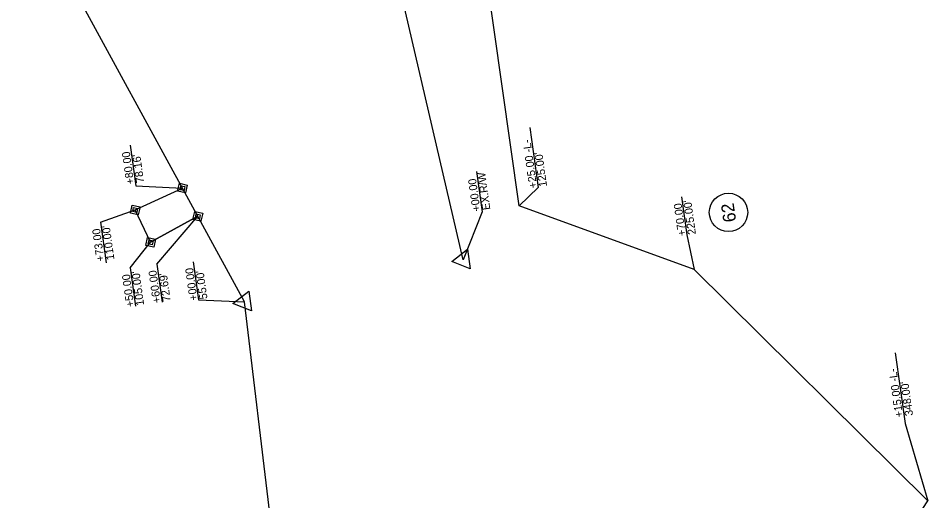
# Model space of a CAD drawing. Extents: x 474184 to 481900, y 489262 to 505659.
# Drawn here: x 477684 to 478252, y 498861 to 499163 of the extents above; entities that cross this region are included whole.
import ezdxf

# ---------------------------------------------------------------- set-up
doc = ezdxf.new("R2010")
doc.units = 0
for name, color, linetype in [('Prop Drainage Structure Outlet Berm Ditch 850 10 Label', 7, 'Continuous'), ('Prop Drainage Structure Pipe CSP 15in', 7, 'Continuous'), ('Prop Drainage Structure Pipe RCP 18in Class IV', 7, 'Continuous'), ('Prop Drainage Structure Pipe RCP 18in Class IV Label', 7, 'Continuous'), ('Prop Drainage Structure Pipe Side Drain 15in Label', 7, 'Continuous'), ('Prop Drainage Structure Pipe Stub Out CELL', 7, 'Continuous'), ('Prop Drainage Structure Plot Symbol 50 Scale', 7, 'Continuous'), ('Prop Earthen Structure Base Ditch Lateral Detail Label', 7, 'Continuous'), ('Prop Earthen Structure False Sump Label', 7, 'Continuous')]:
    doc.layers.add(name, color=color, linetype=linetype)

msp = doc.modelspace()

# ---------------------------------------------------------------- linework, layer by layer
at = {"layer": 'Prop Drainage Structure Outlet Berm Ditch 850 10 Label'}
msp.add_line((477796.28, 499038.73), (477766.76, 499022.46), dxfattribs=at)
msp.add_lwpolyline([(477766.76, 499022.46), (477757.15, 499042.69), (477786.68, 499056.34)], dxfattribs=at)
at = {"layer": 'Prop Drainage Structure Pipe CSP 15in'}
msp.add_line((478127.82, 499041.16), (478127.82, 499041.16), dxfattribs=at)
msp.add_circle((478127.82, 499041.16), 12, dxfattribs=at)
at = {"layer": 'Prop Drainage Structure Pipe RCP 18in Class IV'}
for p, q in [((477786.68, 499056.34), (477786.68, 499056.34)), ((477757.15, 499042.69), (477757.15, 499042.69)), ((477796.28, 499038.73), (477796.28, 499038.73)), ((477766.76, 499022.46), (477766.76, 499022.46)), ((477962.07, 499011.55), (477962.07, 499011.55)), ((477825.37, 498985.31), (477825.37, 498985.31))]:
    msp.add_line(p, q, dxfattribs=at)
for points in [[(477964.78, 499018.23), (477966.49, 499005.87), (477954.92, 499010.54)], [(477828.09, 498992), (477829.8, 498979.64), (477818.23, 498984.31)]]:
    msp.add_lwpolyline(points, close=True, dxfattribs=at)
at = {"layer": 'Prop Drainage Structure Pipe RCP 18in Class IV Label'}
for points in [[(477783.65, 499054.39), (477784.74, 499059.37), (477789.71, 499058.28), (477788.63, 499053.31)], [(477785.17, 499055.36), (477785.71, 499057.85), (477788.2, 499057.31), (477787.66, 499054.82)], [(477754.12, 499040.75), (477755.2, 499045.72), (477760.18, 499044.64), (477759.09, 499039.66)], [(477755.63, 499041.72), (477756.18, 499044.21), (477758.66, 499043.66), (477758.12, 499041.18)], [(477793.25, 499036.78), (477794.33, 499041.76), (477799.31, 499040.67), (477798.22, 499035.7)], [(477794.76, 499037.76), (477795.3, 499040.24), (477797.79, 499039.7), (477797.25, 499037.21)], [(477763.73, 499020.52), (477764.82, 499025.49), (477769.79, 499024.4), (477768.71, 499019.43)], [(477765.25, 499021.49), (477765.79, 499023.97), (477768.28, 499023.43), (477767.74, 499020.94)]]:
    msp.add_lwpolyline(points, close=True, dxfattribs=at)
at = {"layer": 'Prop Drainage Structure Pipe Side Drain 15in Label'}
for p, q in [((477962.07, 499011.55), (477915.07, 499214.11)), ((477935.51, 498068.61), (477825.37, 498985.31))]:
    msp.add_line(p, q, dxfattribs=at)
msp.add_lwpolyline([(477825.37, 498985.31), (477684.05, 499244.74)], dxfattribs=at)
at = {"layer": 'Prop Drainage Structure Pipe Stub Out CELL'}
msp.add_line((478230.71, 498827.55), (478252.33, 498860.85), dxfattribs=at)
for points in [[(477997.01, 499045.21), (477970.76, 499230.34)], [(478252.33, 498860.85), (478106.38, 499005.46), (477997.01, 499045.21)]]:
    msp.add_lwpolyline(points, dxfattribs=at)
at = {"layer": 'Prop Drainage Structure Plot Symbol 50 Scale'}
for p, q in [((477970.34, 499066.72), (477973.86, 499041.45)), ((477973.86, 499041.45), (477962.07, 499011.55)), ((477793.42, 499010.26), (477796.73, 498986.44))]:
    msp.add_line(p, q, dxfattribs=at)
msp.add_lwpolyline([(477796.73, 498986.44), (477825.37, 498985.31)], dxfattribs=at)
at = {"layer": 'Prop Earthen Structure Base Ditch Lateral Detail Label'}
for p, q in [((477753.99, 499083.13), (477757.51, 499057.83)), ((477796.28, 499038.73), (477766.76, 499022.46)), ((477766.76, 499022.46), (477796.28, 499038.73)), ((477735.41, 499034.99), (477738.93, 499009.69)), ((477764.51, 499034.18), (477764.51, 499034.18)), ((477754.02, 499006.45), (477757.33, 498982.63)), ((477770.58, 499008.9), (477773.9, 498985.08))]:
    msp.add_line(p, q, dxfattribs=at)
for points in [[(477757.51, 499057.83), (477786.68, 499056.34)], [(477735.41, 499034.99), (477757.15, 499042.69)], [(477770.58, 499008.9), (477796.28, 499038.73)], [(477754.02, 499006.45), (477766.76, 499022.46)]]:
    msp.add_lwpolyline(points, dxfattribs=at)
at = {"layer": 'Prop Earthen Structure False Sump Label'}
for p, q in [((478003.68, 499094.3), (478008.9, 499056.74)), ((478098.54, 499051), (478101.86, 499027.18)), ((478232, 498953.37), (478238.14, 498909.28))]:
    msp.add_line(p, q, dxfattribs=at)
for points in [[(478008.9, 499056.74), (477997.01, 499045.21)], [(478101.86, 499027.18), (478106.38, 499005.46)], [(478238.14, 498909.28), (478252.33, 498860.85)]]:
    msp.add_lwpolyline(points, dxfattribs=at)

# ---------------------------------------------------------------- texts
at = {"layer": 'Prop Drainage Structure Pipe CSP 15in'}
msp.add_text('62', height=8, rotation=97.9227, dxfattribs=at).set_placement((478132.63, 499035.62))
at = {"layer": 'Prop Drainage Structure Plot Symbol 50 Scale'}
for s, p in [('+00.00 ', (477972.85, 499042.13)), ('EX.R/W', (477979.04, 499042.99)), ('+00.00', (477796.11, 498986.36)), ("55.00'", (477802.3, 498987.22))]:
    msp.add_text(s, height=5, rotation=97.9227, dxfattribs=at).set_placement(p)
at = {"layer": 'Prop Earthen Structure Base Ditch Lateral Detail Label'}
for s, p in [('+80.00', (477756.57, 499059.04)), ("78.16'", (477762.76, 499059.91)), ('+73.00', (477737.99, 499010.9)), ("110.00'", (477744.18, 499011.77)), ('+60.00', (477773.17, 498984.81)), ('+50.00', (477756.6, 498982.36)), ("105.00'", (477762.79, 498983.22)), ("72.69'", (477779.36, 498985.67))]:
    msp.add_text(s, height=5, rotation=97.9227, dxfattribs=at).set_placement(p)
at = {"layer": 'Prop Earthen Structure False Sump Label'}
for s, p in [('+25.00 -L-', (478008.28, 499056.65)), ("125.00'", (478014.47, 499057.52)), ('+70.00', (478101.29, 499026.74)), ("225.00'", (478107.48, 499027.6)), ('+15.00 -L-', (478236.94, 498913.38)), ("348.00'", (478243.13, 498914.24))]:
    msp.add_text(s, height=5, rotation=97.9227, dxfattribs=at).set_placement(p)

doc.saveas('drawing.dxf')
